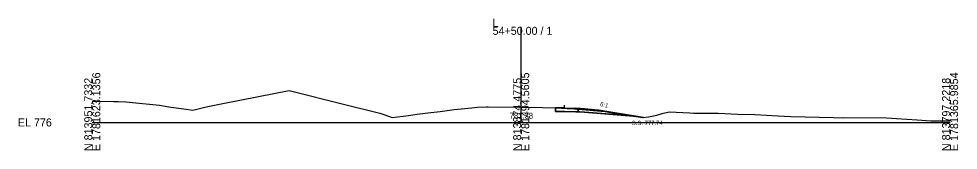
# Model space of a CAD drawing. Extents: x -26 to 7903, y -10 to 9573.
# Drawn here: x 1974.3 to 2302.8, y 5490.3 to 5536.2 of the extents above; entities that cross this region are included whole.
import ezdxf

# ---------------------------------------------------------------- set-up
doc = ezdxf.new("R2010")
doc.units = 0
for name, color, linetype in [('Exist Cross Section Cell', 7, 'Continuous'), ('Exist XS Center Line Elevation Label', 7, 'Continuous'), ('Exist XS Ground Line', 7, 'Continuous'), ('Prop XS Dump Level', 7, 'Continuous'), ('Prop XS Earthwork Shape', 7, 'Continuous'), ('Prop XS EOT Tick Mark', 7, 'Continuous'), ('Prop XS Finish Grade', 7, 'Continuous'), ('Prop XS Finish Grade Earthwork', 7, 'Continuous'), ('Prop XS Finish Grade Paved Shoulder', 7, 'Continuous'), ('Prop XS Finish Grade Pavement', 7, 'Continuous'), ('Prop XS Hydro Fill Slope Data', 7, 'Continuous'), ('Prop XS Pvmt Edge Slope', 7, 'Continuous'), ('Prop XS Side Slope Text', 7, 'Continuous'), ('Prop XS SS Elevation Text', 7, 'Continuous'), ('Prop XS Subgrade Earthwork', 7, 'Continuous'), ('Scratch_Level_3', 7, 'Continuous'), ('Scratch_Level_6', 7, 'Continuous')]:
    doc.layers.add(name, color=color, linetype=linetype)

msp = doc.modelspace()

# ---------------------------------------------------------------- linework, layer by layer
at = {"layer": 'Exist Cross Section Cell'}
for p, q in [((2150, 5500), (2150, 5533.44)), ((2000, 5500), (2150, 5500)), ((2150, 5500), (2300, 5500))]:
    msp.add_line(p, q, dxfattribs=at)
at = {"layer": 'Exist XS Ground Line'}
for p, q in [((2046.86, 5506.92), (2068.83, 5511.15)), ((2068.83, 5511.15), (2087.86, 5506.4)), ((2000, 5507.47), (2001.15, 5507.48)), ((2001.15, 5507.48), (2007.52, 5507.36)), ((2007.52, 5507.36), (2008.63, 5507.34)), ((2008.63, 5507.34), (2009.2, 5507.33)), ((2009.2, 5507.33), (2011.76, 5507.24)), ((2011.76, 5507.24), (2014.08, 5507.01)), ((2014.08, 5507.01), (2023.51, 5506.03)), ((2040.41, 5505.6), (2046.86, 5506.92)), ((2087.86, 5506.4), (2100.59, 5503.3)), ((2023.51, 5506.03), (2027.51, 5505.37)), ((2027.51, 5505.37), (2031.97, 5504.74)), ((2031.97, 5504.74), (2035.15, 5504.34)), ((2035.15, 5504.34), (2038.93, 5505.27)), ((2038.93, 5505.27), (2040.41, 5505.6)), ((2100.59, 5503.3), (2101.97, 5502.82)), ((2110.56, 5502.49), (2113.63, 5502.95)), ((2113.63, 5502.95), (2117.38, 5503.38)), ((2117.38, 5503.38), (2121.72, 5503.87)), ((2121.72, 5503.87), (2126.58, 5504.5)), ((2126.58, 5504.5), (2132.71, 5505.12)), ((2132.71, 5505.12), (2134.59, 5505.3)), ((2134.59, 5505.3), (2137.88, 5505.46)), ((2137.88, 5505.46), (2138.44, 5505.49)), ((2138.44, 5505.49), (2150.21, 5505.38)), ((2150.21, 5505.38), (2157.41, 5505.23)), ((2157.41, 5505.23), (2161.97, 5505.14)), ((2161.97, 5505.14), (2166.03, 5504.94)), ((2166.03, 5504.94), (2167.28, 5504.84)), ((2167.28, 5504.84), (2179.34, 5503.78)), ((2179.34, 5503.78), (2185.12, 5502.77)), ((2197.46, 5502.57), (2199.27, 5503.11)), ((2199.27, 5503.11), (2201.78, 5503.77)), ((2201.78, 5503.77), (2208.95, 5503.35)), ((2208.95, 5503.35), (2210.3, 5503.22)), ((2210.3, 5503.22), (2211.69, 5503.22)), ((2211.69, 5503.22), (2218.91, 5503.2)), ((2218.91, 5503.2), (2225.8, 5502.95)), ((2225.8, 5502.95), (2231.77, 5502.79)), ((2101.97, 5502.82), (2104.94, 5501.69)), ((2104.94, 5501.69), (2110.56, 5502.49)), ((2185.12, 5502.77), (2186.77, 5502.52)), ((2186.77, 5502.52), (2192.49, 5501.7)), ((2192.49, 5501.7), (2194.55, 5502)), ((2194.55, 5502), (2197.46, 5502.57)), ((2231.77, 5502.79), (2239.82, 5502.35)), ((2239.82, 5502.35), (2244.35, 5502.13)), ((2244.35, 5502.13), (2259.28, 5501.77)), ((2259.28, 5501.77), (2262.3, 5501.68)), ((2262.3, 5501.68), (2262.67, 5501.69)), ((2262.67, 5501.69), (2277.73, 5501.6)), ((2277.73, 5501.6), (2281.25, 5501.39)), ((2281.25, 5501.39), (2288.5, 5500.87)), ((2288.5, 5500.87), (2293.3, 5500.6)), ((2293.3, 5500.6), (2299.3, 5500.56)), ((2299.3, 5500.56), (2300, 5500.56))]:
    msp.add_line(p, q, dxfattribs=at)
at = {"layer": 'Prop XS Dump Level'}
for p, q in [((2161.93, 5505.14), (2165.1, 5505.08)), ((2165.1, 5505.08), (2161.93, 5505.14))]:
    msp.add_line(p, q, dxfattribs=at)
at = {"layer": 'Prop XS Earthwork Shape'}
for points in [[(2161.97, 5503.89), (2165.1, 5503.83), (2169.1, 5503.75), (2170.38, 5503.72), (2172.1, 5503.58), (2188.55, 5502.27), (2186.77, 5502.52), (2185.12, 5502.77), (2179.34, 5503.78), (2167.28, 5504.84), (2166.03, 5504.94), (2161.97, 5505.14)], [(2188.55, 5502.27), (2192.49, 5501.7), (2192.79, 5501.74), (2190.64, 5502.1)]]:
    msp.add_lwpolyline(points, close=True, dxfattribs=at)
at = {"layer": 'Prop XS EOT Tick Mark'}
msp.add_line((2165.1, 5505.08), (2165.1, 5506.08), dxfattribs=at)
at = {"layer": 'Prop XS Finish Grade'}
for p, q in [((2169.1, 5505), (2172.1, 5504.76)), ((2172.1, 5504.76), (2177.1, 5504.36)), ((2177.1, 5504.36), (2190.64, 5502.1))]:
    msp.add_line(p, q, dxfattribs=at)
at = {"layer": 'Prop XS Finish Grade Earthwork'}
msp.add_line((2192.79, 5501.74), (2190.64, 5502.1), dxfattribs=at)
at = {"layer": 'Prop XS Finish Grade Paved Shoulder'}
msp.add_line((2165.1, 5505.08), (2169.1, 5505), dxfattribs=at)
at = {"layer": 'Prop XS Finish Grade Pavement'}
msp.add_line((2161.97, 5505.14), (2165.1, 5505.08), dxfattribs=at)
at = {"layer": 'Prop XS Hydro Fill Slope Data'}
msp.add_line((2177.1, 5504.36), (2192.79, 5501.74), dxfattribs=at)
at = {"layer": 'Prop XS Pvmt Edge Slope'}
msp.add_line((2169.1, 5505), (2170.38, 5503.72), dxfattribs=at)
at = {"layer": 'Prop XS Subgrade Earthwork'}
for p, q in [((2161.97, 5503.89), (2161.97, 5505.14)), ((2161.97, 5503.89), (2165.1, 5503.83)), ((2165.1, 5503.83), (2169.1, 5503.75)), ((2169.1, 5503.75), (2170.38, 5503.72)), ((2170.38, 5503.72), (2172.1, 5503.58)), ((2172.1, 5503.58), (2190.64, 5502.1))]:
    msp.add_line(p, q, dxfattribs=at)
at = {"layer": 'Scratch_Level_3'}
for p, q in [((2172.1, 5504.76), (2169.1, 5505)), ((2169.1, 5505), (2170.38, 5503.72)), ((2170.38, 5503.72), (2172.1, 5503.58)), ((2177.1, 5504.36), (2172.1, 5504.76)), ((2172.1, 5503.58), (2190.64, 5502.1)), ((2190.64, 5502.1), (2177.1, 5504.36))]:
    msp.add_line(p, q, dxfattribs=at)
at = {"layer": 'Scratch_Level_6'}
msp.add_lwpolyline([(2161.97, 5503.89), (2161.97, 5505.14), (2166.03, 5504.94), (2167.28, 5504.84), (2179.34, 5503.78), (2185.12, 5502.77), (2186.77, 5502.52), (2188.55, 5502.27), (2172.1, 5503.58), (2170.38, 5503.72), (2169.1, 5503.75), (2165.1, 5503.83)], close=True, dxfattribs=at)

# ---------------------------------------------------------------- texts
at = {"layer": 'Exist Cross Section Cell'}
for s, p in [('L', (2140, 5533.44)), ('54+50.00 / 1', (2140, 5530.64)), ('EL 776', (1974, 5498.6))]:
    msp.add_text(s, height=2.8, dxfattribs=at).set_placement(p)
for s, p in [('E 1781623.1356', (2002.8, 5490)), ('E 1781494.5605', (2152.8, 5490)), ('E 1781365.9854', (2302.8, 5490)), ('N 813951.7332', (2000, 5490)), ('N 813874.4775', (2150, 5490)), ('N 813797.2218', (2300, 5490))]:
    msp.add_text(s, height=2.8, rotation=90, dxfattribs=at).set_placement(p)
at = {"layer": 'Exist XS Center Line Elevation Label'}
msp.add_text('781.38', height=2, dxfattribs=at).set_placement((2145.96, 5501.38))
at = {"layer": 'Prop XS Dump Level'}
for s, height, p in [('Eop', 0.3, (2161.97, 5504.84)), ('Case4', 0.04, (2177.1, 5504.32))]:
    msp.add_text(s, height=height, dxfattribs=at).set_placement(p)
at = {"layer": 'Prop XS Side Slope Text'}
msp.add_text('6:1', height=1.5, rotation=345.9638, dxfattribs=at).set_placement((2177.49, 5505.8))
at = {"layer": 'Prop XS SS Elevation Text'}
msp.add_text('S.S. 777.74', height=1.5, dxfattribs=at).set_placement((2188.69, 5499.08))

doc.saveas('drawing.dxf')
